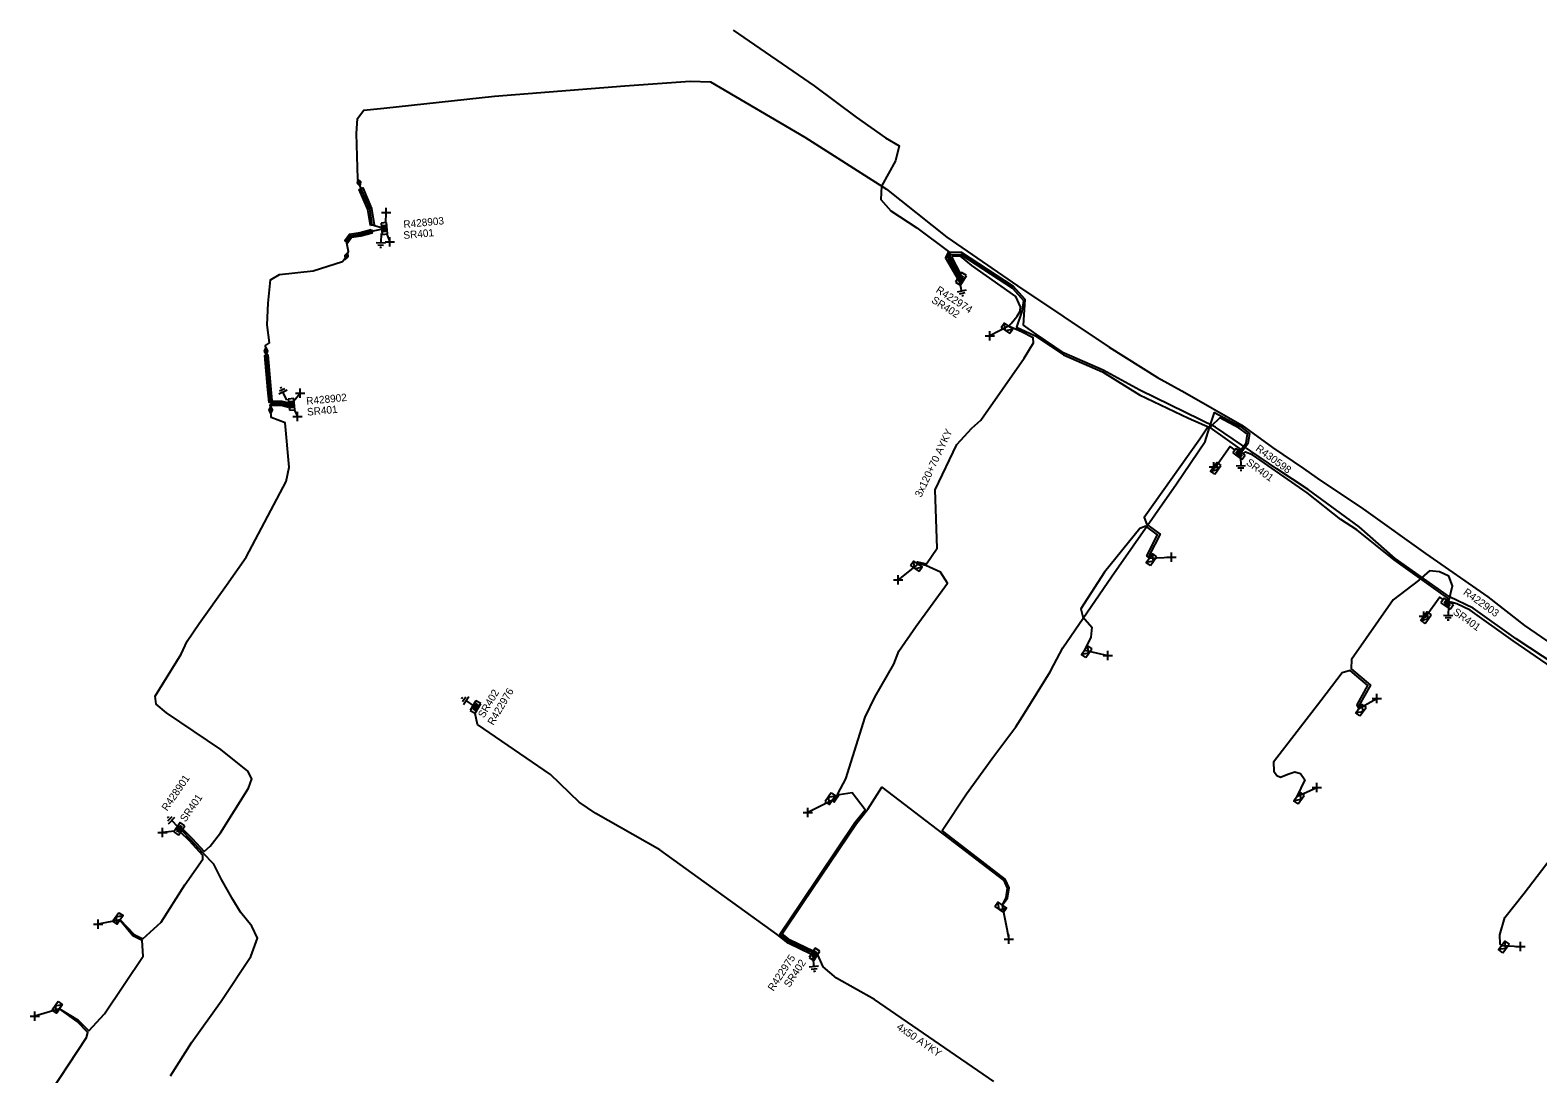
# Model space of a CAD drawing. Extents: x -540466 to -537383, y -1184038 to -1179972.
# Drawn here: x -538699.8 to -538498.5, y -1181199.8 to -1181060.5 of the extents above; entities that cross this region are included whole.
import ezdxf

# ---------------------------------------------------------------- set-up
doc = ezdxf.new("R2010")
doc.units = 0
for name, color, linetype in [('Vrstva 1', 7, 'Continuous'), ('Vrstva 14', 7, 'Continuous'), ('Vrstva 15', 7, 'Continuous'), ('Vrstva 19', 7, 'Continuous'), ('Vrstva 20', 7, 'Continuous'), ('Vrstva 28', 7, 'Continuous'), ('Vrstva 29', 7, 'Continuous'), ('Vrstva 30', 7, 'Continuous'), ('Vrstva 31', 7, 'Continuous'), ('Vrstva 34', 7, 'Continuous'), ('Vrstva 4', 7, 'Continuous'), ('Vrstva 5', 7, 'Continuous'), ('Vrstva 52', 7, 'Continuous'), ('Vrstva 59', 7, 'Continuous'), ('Vrstva 6', 7, 'Continuous'), ('Vrstva 8', 7, 'Continuous'), ('Vrstva 9', 7, 'Continuous')]:
    doc.layers.add(name, color=color, linetype=linetype)

# ---------------------------------------------------------------- blocks, each defined once
blk = doc.blocks.new('NN870')
at = {"layer": 'Vrstva 4'}
for points in [[(0, -0.25), (0.5, 0), (0, 0.25), (-0.5, 0), (0, -0.25)], [(0.37, 0), (0, 0.19), (-0.36, 0), (0, -0.19), (0.37, 0)], [(0.24, 0), (0, 0.12), (-0.25, 0), (0, -0.12), (0.24, 0)], [(0.12, 0), (0, 0.06), (-0.13, 0), (0, -0.06), (0.12, 0)]]:
    blk.add_lwpolyline(points, dxfattribs=at)
blk = doc.blocks.new('NN800')
at = {"layer": 'Vrstva 1'}
for points in [[(-0.44, 0.44), (0.44, -0.44)], [(-0.44, -0.44), (0.44, 0.44)]]:
    blk.add_lwpolyline(points, dxfattribs=at)
blk = doc.blocks.new('NN620')
at = {"layer": 'Vrstva 8'}
for points in [[(0.75, 0), (-0.75, 0)], [(-0.75, 0), (-0.75, -0.75)], [(0.75, -0.75), (0.75, 0)], [(-0.75, -0.75), (0.75, -0.75)], [(0.37, -0.18), (-0.38, -0.18)], [(-0.38, -0.18), (-0.38, -0.56)], [(-0.38, -0.56), (0.37, -0.56)], [(0.32, -0.23), (-0.33, -0.23)], [(-0.33, -0.23), (-0.33, -0.51)], [(-0.33, -0.51), (0.32, -0.51)], [(0.27, -0.27), (-0.28, -0.27)], [(-0.28, -0.27), (-0.28, -0.46)], [(-0.28, -0.46), (0.27, -0.46)], [(0.23, -0.32), (-0.23, -0.32)], [(-0.23, -0.32), (-0.23, -0.42)], [(-0.23, -0.42), (0.23, -0.42)], [(-0.19, -0.37), (0.19, -0.37)], [(0.23, -0.42), (0.23, -0.32)], [(0.27, -0.46), (0.27, -0.27)], [(0.32, -0.51), (0.32, -0.23)], [(0.37, -0.56), (0.37, -0.18)]]:
    blk.add_lwpolyline(points, dxfattribs=at)
blk = doc.blocks.new('NN630')
at = {"layer": 'Vrstva 9'}
for points in [[(0, -0.7), (-0.7, 0)], [(-0.7, -0.7), (-0.7, 0), (0.7, 0), (0.7, -0.7)], [(-0.7, -0.7), (0.7, -0.7)], [(0, -0.7), (0.7, 0)]]:
    blk.add_lwpolyline(points, dxfattribs=at)
blk = doc.blocks.new('NN810')
at = {"layer": 'Vrstva 14'}
for points in [[(0.63, -1.89), (-0.62, -1.89)], [(0, -0.64), (0, -1.89)], [(0.39, -2.2), (-0.4, -2.2)], [(0, -2.52), (-0.12, -2.52)], [(0.14, -2.52), (0, -2.52)]]:
    blk.add_lwpolyline(points, dxfattribs=at)

msp = doc.modelspace()

# ---------------------------------------------------------------- linework, layer by layer
at = {"layer": 'Vrstva 20'}
for points in [[(-538654.37, -1181086.6), (-538654.7, -1181084.45), (-538655.85, -1181081.78), (-538655.39, -1181081.58), (-538654.22, -1181084.31), (-538653.87, -1181086.52)], [(-538654.26, -1181087.12), (-538654.13, -1181087.61), (-538655.64, -1181088.02), (-538656.88, -1181088.21), (-538657.37, -1181088.89), (-538657.79, -1181088.59), (-538657.16, -1181087.75), (-538655.74, -1181087.53)], [(-538667.52, -1181109.95), (-538667.89, -1181110.21), (-538668.07, -1181108.53), (-538668.45, -1181103.95), (-538668.07, -1181103.87), (-538667.68, -1181108.49)], [(-538667.5, -1181110.04), (-538666.2, -1181110.03), (-538665.42, -1181110.22), (-538665.45, -1181110.85), (-538666.28, -1181110.63), (-538667.53, -1181110.64)]]:
    msp.add_lwpolyline(points, close=True, dxfattribs=at)
at = {"layer": 'Vrstva 5'}
for points in [[(-538605.96, -1181060.52), (-538595.13, -1181067.97), (-538589.51, -1181072.15), (-538585.62, -1181074.87), (-538583.77, -1181075.97), (-538584.28, -1181077.94), (-538586.12, -1181081.36), (-538586.23, -1181083.11), (-538584.88, -1181084.63), (-538581.43, -1181086.91), (-538577.21, -1181090.05), (-538577.58, -1181090.89), (-538576.04, -1181093.57)], [(-538655.9, -1181080.86), (-538656.05, -1181080.35), (-538656.21, -1181074.3), (-538656.1, -1181072.29), (-538655.23, -1181071.19), (-538652.56, -1181070.94), (-538637.79, -1181069.35), (-538620.41, -1181067.95), (-538611.66, -1181067.32), (-538608.96, -1181067.4), (-538596.38, -1181074.81), (-538585.48, -1181081.74), (-538577.4, -1181088.15), (-538567.98, -1181094.64), (-538555.74, -1181102.81), (-538549.31, -1181106.86), (-538545.63, -1181108.86), (-538538.04, -1181113.24), (-538533.92, -1181116.2), (-538529.78, -1181119.03), (-538527.97, -1181120.33), (-538521.77, -1181124.45), (-538513.51, -1181130.36), (-538505.17, -1181136.15), (-538500.3, -1181139.96), (-538490.23, -1181146.86)], [(-538652.9, -1181086.9), (-538654.12, -1181086.56), (-538654.46, -1181084.38), (-538655.62, -1181081.68), (-538655.9, -1181080.86)], [(-538657.56, -1181090.67), (-538657.31, -1181090.05), (-538657.57, -1181088.74), (-538657.02, -1181087.98), (-538655.69, -1181087.77), (-538654.19, -1181087.37), (-538652.92, -1181087.09)], [(-538665.27, -1181110.47), (-538666.23, -1181110.23), (-538667.61, -1181110.24), (-538667.7, -1181110.08), (-538667.88, -1181108.51), (-538668.3, -1181103.35), (-538668.36, -1181102.6), (-538667.84, -1181102.27), (-538668.16, -1181099.87), (-538668, -1181096.96), (-538667.71, -1181093.84), (-538666.48, -1181093.11), (-538662, -1181092.66), (-538658.08, -1181091.38), (-538657.56, -1181090.67)], [(-538496.05, -1181145.29), (-538501.42, -1181141.76), (-538507.16, -1181137.67), (-538510.32, -1181136.16), (-538517.55, -1181131.02), (-538522.38, -1181126.81), (-538529.19, -1181121.84), (-538533.36, -1181119.09), (-538541.56, -1181113.52), (-538551.67, -1181108.58), (-538556.54, -1181105.89), (-538561.73, -1181103.62), (-538565.47, -1181101.11), (-538567.17, -1181099.88), (-538566.94, -1181096.46), (-538568.5, -1181094.75), (-538575.46, -1181090.19), (-538577, -1181090.17), (-538577.3, -1181090.88), (-538575.85, -1181093.49)], [(-538575.73, -1181093.29), (-538577.03, -1181090.88), (-538576.84, -1181090.43), (-538575.54, -1181090.44), (-538568.66, -1181094.95), (-538567.16, -1181096.58), (-538567.32, -1181097.5), (-538567.39, -1181098.06), (-538568.1, -1181100.14), (-538565.69, -1181101.27), (-538561.85, -1181103.84), (-538556.65, -1181106.11), (-538551.68, -1181109.19), (-538545.14, -1181112.32), (-538542.32, -1181113.55), (-538538.31, -1181116.39), (-538538.44, -1181116.59)], [(-538569.2, -1181100.01), (-538568.82, -1181099.65), (-538568.04, -1181098.71), (-538567.63, -1181098.02), (-538567.56, -1181097.46), (-538568.21, -1181096.05), (-538574.06, -1181091.91), (-538575.61, -1181090.68), (-538576.67, -1181090.68), (-538576.76, -1181090.88), (-538575.6, -1181093.09)], [(-538581.28, -1181131.8), (-538581.31, -1181131.47), (-538580.15, -1181131.73), (-538578.71, -1181129.65), (-538578.95, -1181121.88), (-538576.08, -1181115.8), (-538574.06, -1181113.66), (-538572.86, -1181112.58), (-538567.07, -1181104.28), (-538565.84, -1181102.25), (-538565.88, -1181101.6), (-538567.45, -1181100.8), (-538568.87, -1181100.16), (-538569.2, -1181100.01)], [(-538679.43, -1181167.11), (-538678.14, -1181168.4), (-538676.56, -1181170.14), (-538675.74, -1181169.42), (-538674.4, -1181167.66), (-538670.64, -1181161.67), (-538670.21, -1181160.44), (-538670.75, -1181159.42), (-538674.35, -1181156.55), (-538681.57, -1181151.63), (-538682.98, -1181150.47), (-538683.1, -1181149.41), (-538679.65, -1181143.81), (-538678.85, -1181142.06), (-538677.22, -1181139.69), (-538673.59, -1181134.58), (-538670.97, -1181130.84), (-538665.61, -1181120.75), (-538665.22, -1181118.83), (-538665.76, -1181112.94), (-538667.61, -1181112.2), (-538667.68, -1181111.23), (-538667.74, -1181110.52), (-538667.67, -1181110.44), (-538666.25, -1181110.43), (-538665.24, -1181110.68)], [(-538570.02, -1181177.3), (-538569.3, -1181176.37), (-538569.1, -1181175), (-538569.61, -1181173.84), (-538577.79, -1181167.57), (-538578.04, -1181167.32), (-538574.8, -1181162.43), (-538571.28, -1181157.61), (-538568.21, -1181153.5), (-538567.05, -1181151.68), (-538563.61, -1181146.17), (-538563.11, -1181145.21), (-538561.93, -1181142.95), (-538555.42, -1181133.47), (-538546.75, -1181121.06), (-538542.93, -1181115.42), (-538542.35, -1181113.53), (-538541.66, -1181111.57), (-538538.22, -1181113.41), (-538536.99, -1181114.35), (-538537.21, -1181115.73), (-538538.08, -1181116.85)], [(-538538.28, -1181116.71), (-538537.44, -1181115.6), (-538537.29, -1181114.46), (-538538.39, -1181113.64), (-538540.99, -1181112.26), (-538542.15, -1181113.44), (-538542.34, -1181113.53), (-538542.59, -1181113.63), (-538542.65, -1181113.66), (-538543.64, -1181115.12), (-538551.07, -1181125.56), (-538550.71, -1181126.52), (-538548.95, -1181127.8), (-538550.41, -1181130.62), (-538550.38, -1181130.99), (-538550.71, -1181130.66), (-538549.27, -1181127.88), (-538550.85, -1181126.72), (-538551.67, -1181127.01), (-538556.35, -1181132.88), (-538559.51, -1181137.77), (-538559.26, -1181138.84), (-538558.05, -1181140.18), (-538558.19, -1181141.55), (-538559.04, -1181143.27)], [(-538510.59, -1181136.59), (-538510.55, -1181136.31), (-538517.7, -1181131.22), (-538522.66, -1181127.22), (-538524.81, -1181125.81), (-538529.29, -1181122.28), (-538536.61, -1181117.22), (-538537.56, -1181116.84), (-538537.86, -1181117.01)], [(-538595.41, -1181183.64), (-538598.47, -1181182.18), (-538599.71, -1181181.18), (-538596.87, -1181176.93), (-538589.68, -1181166.25), (-538588.32, -1181164.57), (-538590.04, -1181162.29), (-538591.78, -1181162.58), (-538592.47, -1181163.54), (-538592.67, -1181163.3), (-538592.61, -1181163.3), (-538591.98, -1181162.44), (-538590.88, -1181160.44), (-538588.32, -1181152.22), (-538587.02, -1181149.55), (-538584.47, -1181145.14), (-538583.83, -1181143.42), (-538581.5, -1181140.05), (-538577.31, -1181134.34), (-538578.25, -1181132.86), (-538580.21, -1181131.97), (-538581.24, -1181131.74), (-538581.28, -1181131.8)], [(-538510.39, -1181136.73), (-538509.93, -1181134.67), (-538510.38, -1181133.4), (-538511.65, -1181132.83), (-538512.99, -1181132.69), (-538514.44, -1181133.99), (-538517.84, -1181136.57), (-538523.39, -1181144.5), (-538523.43, -1181145.77), (-538520.87, -1181147.93), (-538522.36, -1181150.6), (-538522.42, -1181151.07), (-538522.64, -1181150.58), (-538521.19, -1181147.99), (-538523.57, -1181145.97), (-538524.64, -1181146.3), (-538527.49, -1181150.02), (-538533.82, -1181158.21), (-538533.74, -1181159.4), (-538533.34, -1181159.98), (-538532.85, -1181160.23), (-538531.91, -1181159.81), (-538530.95, -1181159.52), (-538530.19, -1181159.71), (-538529.64, -1181160.56), (-538530.68, -1181162.81)], [(-538483.79, -1181155.85), (-538483.92, -1181155.25), (-538487.34, -1181153.37), (-538491.32, -1181150.27), (-538494.15, -1181148.37), (-538496.55, -1181145.64), (-538501.8, -1181142.03), (-538507.54, -1181137.93), (-538509.31, -1181137.09), (-538510.15, -1181136.85), (-538510.18, -1181136.88)], [(-538595.55, -1181183.85), (-538598.6, -1181182.39), (-538600.05, -1181181.23), (-538615.72, -1181169.94), (-538620.97, -1181166.95), (-538624.26, -1181165.05), (-538626.5, -1181163.54), (-538630.31, -1181159.86), (-538640.09, -1181153.21), (-538640.38, -1181151.72)], [(-538503.34, -1181182.67), (-538503.53, -1181182.53), (-538503.58, -1181181.25), (-538502.9, -1181178.94), (-538500.34, -1181175.72), (-538495.01, -1181168.71), (-538489.42, -1181161.49), (-538488.21, -1181162.01), (-538489.06, -1181161.06), (-538484.86, -1181155.24), (-538483.84, -1181154.59), (-538483.51, -1181156.03)], [(-538595.27, -1181183.43), (-538598.34, -1181181.97), (-538599.38, -1181181.13), (-538596.67, -1181177.07), (-538589.48, -1181166.4), (-538588.13, -1181164.73), (-538587.94, -1181164.49), (-538586.1, -1181161.57), (-538577.94, -1181167.77), (-538569.81, -1181174), (-538569.36, -1181175.04), (-538569.54, -1181176.29), (-538570.02, -1181177.3)], [(-538698.2, -1181203.95), (-538692.25, -1181194.96), (-538692.08, -1181194.32), (-538693.53, -1181192.85), (-538695.88, -1181191.15), (-538695.89, -1181191.12), (-538693.37, -1181192.67), (-538691.95, -1181194.09), (-538689.88, -1181191.82), (-538684.72, -1181184.09), (-538684.83, -1181182.03), (-538686.06, -1181181.4), (-538687.77, -1181179.33), (-538687.76, -1181179.28), (-538685.9, -1181181.2), (-538684.74, -1181181.79), (-538682.31, -1181179.57), (-538679.16, -1181174.58), (-538676.72, -1181171.15), (-538676.74, -1181170.69), (-538678.5, -1181168.74), (-538679.7, -1181167.54)], [(-538681.06, -1181200.08), (-538678.21, -1181195.6), (-538674.29, -1181190.12), (-538670.32, -1181184.15), (-538669.44, -1181181.69), (-538670.2, -1181180.09), (-538671.73, -1181178.25), (-538672.73, -1181176.53), (-538674.25, -1181173.86), (-538675.28, -1181171.82), (-538676.75, -1181170.3), (-538678.32, -1181168.57), (-538679.56, -1181167.33)], [(-538571.14, -1181200.82), (-538587.07, -1181189.91), (-538592.13, -1181187.04), (-538593.91, -1181185.52), (-538594.64, -1181183.93)]]:
    msp.add_lwpolyline(points, dxfattribs=at)
at = {"layer": 'Vrstva 52'}
for points in [[(-538538.98, -1181116.54), (-538539.58, -1181116.1), (-538541.59, -1181118.95), (-538541.79, -1181118.8)], [(-538511.17, -1181136.51), (-538511.58, -1181136.21), (-538513.51, -1181138.88), (-538513.73, -1181138.72)]]:
    msp.add_lwpolyline(points, dxfattribs=at)
at = {"layer": 'Vrstva 59'}
for points in [[(-538652.3, -1181086.29), (-538652.25, -1181084.85)], [(-538652.21, -1181087.67), (-538651.77, -1181088.78)], [(-538569.2, -1181100.01), (-538571.66, -1181101.31)], [(-538664.6, -1181109.99), (-538663.74, -1181108.99)], [(-538664.55, -1181111.15), (-538664.08, -1181112.07)], [(-538550.38, -1181130.99), (-538547.44, -1181130.86)], [(-538581.28, -1181131.8), (-538583.93, -1181133.88)], [(-538559.04, -1181143.27), (-538555.93, -1181143.98)], [(-538522.42, -1181151.07), (-538520.03, -1181149.74)], [(-538530.68, -1181162.81), (-538528.01, -1181161.59)], [(-538592.67, -1181163.3), (-538595.98, -1181164.92)], [(-538680.52, -1181167.44), (-538682.12, -1181167.6)], [(-538570.02, -1181177.3), (-538569.12, -1181181.86)], [(-538687.76, -1181179.28), (-538690.7, -1181179.86)], [(-538503.34, -1181182.67), (-538500.81, -1181182.84)], [(-538695.89, -1181191.12), (-538699.16, -1181192.12)]]:
    msp.add_lwpolyline(points, dxfattribs=at)

# ---------------------------------------------------------------- block references
at = {"layer": 'Vrstva 15'}
for p, rotation in [((-538652.88, -1181087.03), -2.841644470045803), ((-538575.84, -1181093.51), 12.25819442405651), ((-538665.26, -1181110.5), -155.70018602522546), ((-538538.21, -1181116.79), 1.2139777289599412), ((-538510.4, -1181136.76), -2.2265971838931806), ((-538640.01, -1181151.04), -123.9979777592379), ((-538679.56, -1181167.33), -135), ((-538595.39, -1181183.65), 6.971077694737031)]:
    msp.add_blockref('NN810', p, dxfattribs=dict(at, rotation=rotation))
at = {"layer": 'Vrstva 19'}
for p, rotation in [((-538655.9, -1181080.86), -71.1468416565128), ((-538657.56, -1181090.67), 68.03943613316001), ((-538668.3, -1181103.35), -85.26206946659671), ((-538667.68, -1181111.23), -86.06087773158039)]:
    msp.add_blockref('NN870', p, dxfattribs=dict(at, rotation=rotation))
at = {"layer": 'Vrstva 28'}
for p, rotation in [((-538652.88, -1181087.03), 95.45960829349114), ((-538575.84, -1181093.51), 57.463202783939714), ((-538665.26, -1181110.51), 95.45960829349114), ((-538538.2, -1181116.79), -36.05846382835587), ((-538510.4, -1181136.76), -35.658513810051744), ((-538640.01, -1181151.04), -120.57935280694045), ((-538679.56, -1181167.33), -124.53812218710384), ((-538595.39, -1181183.65), 56.56914996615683)]:
    msp.add_blockref('NN620', p, dxfattribs=dict(at, rotation=rotation))
at = {"layer": 'Vrstva 31'}
for p, rotation in [((-538569.2, -1181100.01), -34.81757497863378), ((-538541.79, -1181118.81), 54.813294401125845), ((-538581.28, -1181131.8), -34.81757486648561), ((-538550.38, -1181130.99), 54.813294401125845), ((-538513.73, -1181138.72), 54.14652218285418), ((-538559.04, -1181143.27), 54.813294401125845), ((-538522.42, -1181151.07), 54.14652218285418), ((-538592.67, -1181163.3), -124.7560027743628), ((-538530.68, -1181162.81), 54.14652215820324), ((-538570.02, -1181177.3), -34.550255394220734), ((-538687.76, -1181179.28), -124.47099720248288), ((-538503.34, -1181182.67), 54.14652218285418), ((-538695.89, -1181191.13), -124.47099720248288)]:
    msp.add_blockref('NN630', p, dxfattribs=dict(at, rotation=rotation))
at = {"layer": 'Vrstva 34'}
for p, rotation in [((-538652.25, -1181084.85), 45), ((-538651.77, -1181088.78), 45), ((-538571.66, -1181101.31), 45), ((-538663.74, -1181108.99), 45), ((-538664.08, -1181112.07), 45), ((-538541.79, -1181118.81), 45), ((-538547.44, -1181130.86), 45), ((-538583.93, -1181133.88), 45), ((-538513.73, -1181138.72), 45), ((-538555.93, -1181143.98), 45), ((-538520.03, -1181149.74), 45), ((-538528.01, -1181161.59), 45.00000009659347), ((-538595.98, -1181164.92), 45), ((-538682.12, -1181167.6), 45), ((-538690.7, -1181179.86), 45), ((-538569.12, -1181181.86), 45), ((-538500.81, -1181182.84), 45), ((-538699.16, -1181192.12), 45)]:
    msp.add_blockref('NN800', p, dxfattribs=dict(at, rotation=rotation))

# ---------------------------------------------------------------- texts
at = {"layer": 'Vrstva 29'}
for s, rotation, p in [('R428903', 5.46, (-538649.91, -1181086.94)), ('R422974', 327.463, (-538578.97, -1181095.44)), ('R428902', 5.46, (-538662.88, -1181110.52)), ('R430598', 323.942, (-538536.28, -1181116.56)), ('R422903', 324.341, (-538508.56, -1181135.74)), ('R422976', 59.421, (-538637.95, -1181153.38)), ('R428901', 55.462, (-538681.5, -1181164.82)), ('R422975', 56.569, (-538600.57, -1181188.86))]:
    msp.add_text(s, height=1, rotation=rotation, dxfattribs=at).set_placement(p)
at = {"layer": 'Vrstva 30'}
for s, rotation, p in [('SR401', 5.46, (-538649.91, -1181088.4)), ('SR402', 327.463, (-538579.55, -1181096.8)), ('SR401', 5.46, (-538662.78, -1181111.98)), ('SR401', 323.942, (-538537.55, -1181118.42)), ('SR401', 324.341, (-538509.93, -1181138.38)), ('SR402', 59.421, (-538639.22, -1181152.41)), ('SR401', 55.462, (-538679.05, -1181166.29)), ('SR402', 56.569, (-538598.42, -1181188.37))]:
    msp.add_text(s, height=1, rotation=rotation, dxfattribs=at).set_placement(p)
at = {"layer": 'Vrstva 6'}
for s, rotation, p in [('3x120+70 AYKY', 64.731, (-538580.84, -1181122.95)), ('4x50 AYKY', 325.594, (-538584.21, -1181193.77))]:
    msp.add_text(s, height=1, rotation=rotation, dxfattribs=at).set_placement(p)

doc.saveas('drawing.dxf')
